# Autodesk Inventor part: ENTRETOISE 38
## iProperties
Created: 2004-11
Part Number: ENTRETOISE 38
Document SubType Name: Modeling
Designer: Bruno
Manufacturer: Standard
Standards Organization: Custom
Author: Bruno
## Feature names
1. Base1
